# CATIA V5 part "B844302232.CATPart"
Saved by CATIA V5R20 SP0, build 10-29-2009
Part number: B844302232
Revision: 2
Definition: design
Nomenclature: B844302232
Source: made
Description: NOT SPECIFIED
Bounding box of the stored display mesh (mm): x -24.5 to 24.5, y -24.5 to 24.5, z -22 to 32
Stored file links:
  C:\Users\Utente\Desktop\3D files B844\B844302232.CATPart
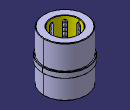
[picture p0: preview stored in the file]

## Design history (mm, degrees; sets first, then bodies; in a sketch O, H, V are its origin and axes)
Body1 "MANIFOLD_SOLID_BREP #38" (main body)
  Solid1: solid without history
Body2 "MANIFOLD_SOLID_BREP #76"
  Solid2: solid without history
Body3 "MANIFOLD_SOLID_BREP #114"
  Solid3: solid without history
Body4 "MANIFOLD_SOLID_BREP #152"
  Solid4: solid without history
Body5 "MANIFOLD_SOLID_BREP #190"
  Solid5: solid without history
Body6 "MANIFOLD_SOLID_BREP #228"
  Solid6: solid without history
Body7 "MANIFOLD_SOLID_BREP #266"
  Solid7: solid without history
Body8 "MANIFOLD_SOLID_BREP #304"
  Solid8: solid without history
Body9 "MANIFOLD_SOLID_BREP #2405"
  Solid9: solid without history
Body10 "MANIFOLD_SOLID_BREP #2443"
  Solid10: solid without history
Body11 "MANIFOLD_SOLID_BREP #2481"
  Solid11: solid without history
Body12 "MANIFOLD_SOLID_BREP #2519"
  Solid12: solid without history
Body13 "MANIFOLD_SOLID_BREP #2557"
  Solid13: solid without history
Body14 "MANIFOLD_SOLID_BREP #2595"
  Solid14: solid without history
Body15 "MANIFOLD_SOLID_BREP #2633"
  Solid15: solid without history
Body16 "MANIFOLD_SOLID_BREP #2671"
  Solid16: solid without history
Body17 "MANIFOLD_SOLID_BREP #2709"
  Solid17: solid without history
Body18 "MANIFOLD_SOLID_BREP #2747"
  Solid18: solid without history
Body19 "MANIFOLD_SOLID_BREP #2785"
  Solid19: solid without history
Body20 "MANIFOLD_SOLID_BREP #2823"
  Solid20: solid without history
Body21 "MANIFOLD_SOLID_BREP #2861"
  Solid21: solid without history
Body22 "MANIFOLD_SOLID_BREP #2899"
  Solid22: solid without history
Body23 "MANIFOLD_SOLID_BREP #2937"
  Solid23: solid without history
Body24 "MANIFOLD_SOLID_BREP #2975"
  Solid24: solid without history
Body25 "MANIFOLD_SOLID_BREP #3013"
  Solid25: solid without history
Body26 "MANIFOLD_SOLID_BREP #3051"
  Solid26: solid without history
Body27 "MANIFOLD_SOLID_BREP #3089"
  Solid27: solid without history
Body28 "MANIFOLD_SOLID_BREP #3127"
  Solid28: solid without history
Body29 "MANIFOLD_SOLID_BREP #3165"
  Solid29: solid without history
Body30 "MANIFOLD_SOLID_BREP #3203"
  Solid30: solid without history
Body31 "MANIFOLD_SOLID_BREP #3241"
  Solid31: solid without history
Body32 "MANIFOLD_SOLID_BREP #3279"
  Solid32: solid without history
Body33 "MANIFOLD_SOLID_BREP #3317"
  Solid33: solid without history
Body34 "MANIFOLD_SOLID_BREP #3355"
  Solid34: solid without history
Body35 "MANIFOLD_SOLID_BREP #3393"
  Solid35: solid without history
Body36 "MANIFOLD_SOLID_BREP #3431"
  Solid36: solid without history
Body37 "MANIFOLD_SOLID_BREP #3469"
  Solid37: solid without history
Body38 "MANIFOLD_SOLID_BREP #3507"
  Solid38: solid without history
Body39 "MANIFOLD_SOLID_BREP #3545"
  Solid39: solid without history
Body40 "MANIFOLD_SOLID_BREP #3583"
  Solid40: solid without history
Body41 "MANIFOLD_SOLID_BREP #3621"
  Solid41: solid without history
Body42 "MANIFOLD_SOLID_BREP #3659"
  Solid42: solid without history
Body43 "MANIFOLD_SOLID_BREP #3697"
  Solid43: solid without history
Body44 "MANIFOLD_SOLID_BREP #3735"
  Solid44: solid without history
Body45 "MANIFOLD_SOLID_BREP #3773"
  Solid45: solid without history
Body46 "MANIFOLD_SOLID_BREP #3811"
  Solid46: solid without history
Body47 "MANIFOLD_SOLID_BREP #3849"
  Solid47: solid without history
Body48 "MANIFOLD_SOLID_BREP #3887"
  Solid48: solid without history
Body49 "MANIFOLD_SOLID_BREP #3925"
  Solid49: solid without history
Body50 "MANIFOLD_SOLID_BREP #3963"
  Solid50: solid without history
Body51 "MANIFOLD_SOLID_BREP #4001"
  Solid51: solid without history
Body52 "MANIFOLD_SOLID_BREP #4039"
  Solid52: solid without history
Body53 "MANIFOLD_SOLID_BREP #4077"
  Solid53: solid without history
Body54 "MANIFOLD_SOLID_BREP #4115"
  Solid54: solid without history
Body55 "MANIFOLD_SOLID_BREP #4153"
  Solid55: solid without history
Body56 "MANIFOLD_SOLID_BREP #4191"
  Solid56: solid without history
Body57 "MANIFOLD_SOLID_BREP #4229"
  Solid57: solid without history
Body58 "MANIFOLD_SOLID_BREP #4267"
  Solid58: solid without history
Body59 "MANIFOLD_SOLID_BREP #4305"
  Solid59: solid without history
Body60 "MANIFOLD_SOLID_BREP #4343"
  Solid60: solid without history
Body61 "MANIFOLD_SOLID_BREP #4381"
  Solid61: solid without history
Body62 "MANIFOLD_SOLID_BREP #4419"
  Solid62: solid without history
Body63 "MANIFOLD_SOLID_BREP #4457"
  Solid63: solid without history
Body64 "MANIFOLD_SOLID_BREP #4495"
  Solid64: solid without history
Body65 "MANIFOLD_SOLID_BREP #4533"
  Solid65: solid without history
Body66 "MANIFOLD_SOLID_BREP #4571"
  Solid66: solid without history
Body67 "MANIFOLD_SOLID_BREP #4609"
  Solid67: solid without history
Body68 "MANIFOLD_SOLID_BREP #4647"
  Solid68: solid without history
Body69 "MANIFOLD_SOLID_BREP #4685"
  Solid69: solid without history
Body70 "MANIFOLD_SOLID_BREP #4723"
  Solid70: solid without history
Body71 "MANIFOLD_SOLID_BREP #4761"
  Solid71: solid without history
Body72 "MANIFOLD_SOLID_BREP #4799"
  Solid72: solid without history
Body73 "MANIFOLD_SOLID_BREP #4837"
  Solid73: solid without history
Body74 "MANIFOLD_SOLID_BREP #4875"
  Solid74: solid without history
Body75 "MANIFOLD_SOLID_BREP #4913"
  Solid75: solid without history
Body76 "MANIFOLD_SOLID_BREP #4951"
  Solid76: solid without history
Body77 "MANIFOLD_SOLID_BREP #4989"
  Solid77: solid without history
Body78 "MANIFOLD_SOLID_BREP #5027"
  Solid78: solid without history
Body79 "MANIFOLD_SOLID_BREP #5065"
  Solid79: solid without history
Body80 "MANIFOLD_SOLID_BREP #5103"
  Solid80: solid without history
Body81 "MANIFOLD_SOLID_BREP #5141"
  Solid81: solid without history
Body82 "MANIFOLD_SOLID_BREP #5179"
  Solid82: solid without history
Body83 "MANIFOLD_SOLID_BREP #5217"
  Solid83: solid without history
Body84 "MANIFOLD_SOLID_BREP #5255"
  Solid84: solid without history
Body85 "MANIFOLD_SOLID_BREP #5293"
  Solid85: solid without history
Body86 "MANIFOLD_SOLID_BREP #5331"
  Solid86: solid without history
Body87 "MANIFOLD_SOLID_BREP #5369"
  Solid87: solid without history
Body88 "MANIFOLD_SOLID_BREP #5407"
  Solid88: solid without history
Body89 "MANIFOLD_SOLID_BREP #5445"
  Solid89: solid without history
